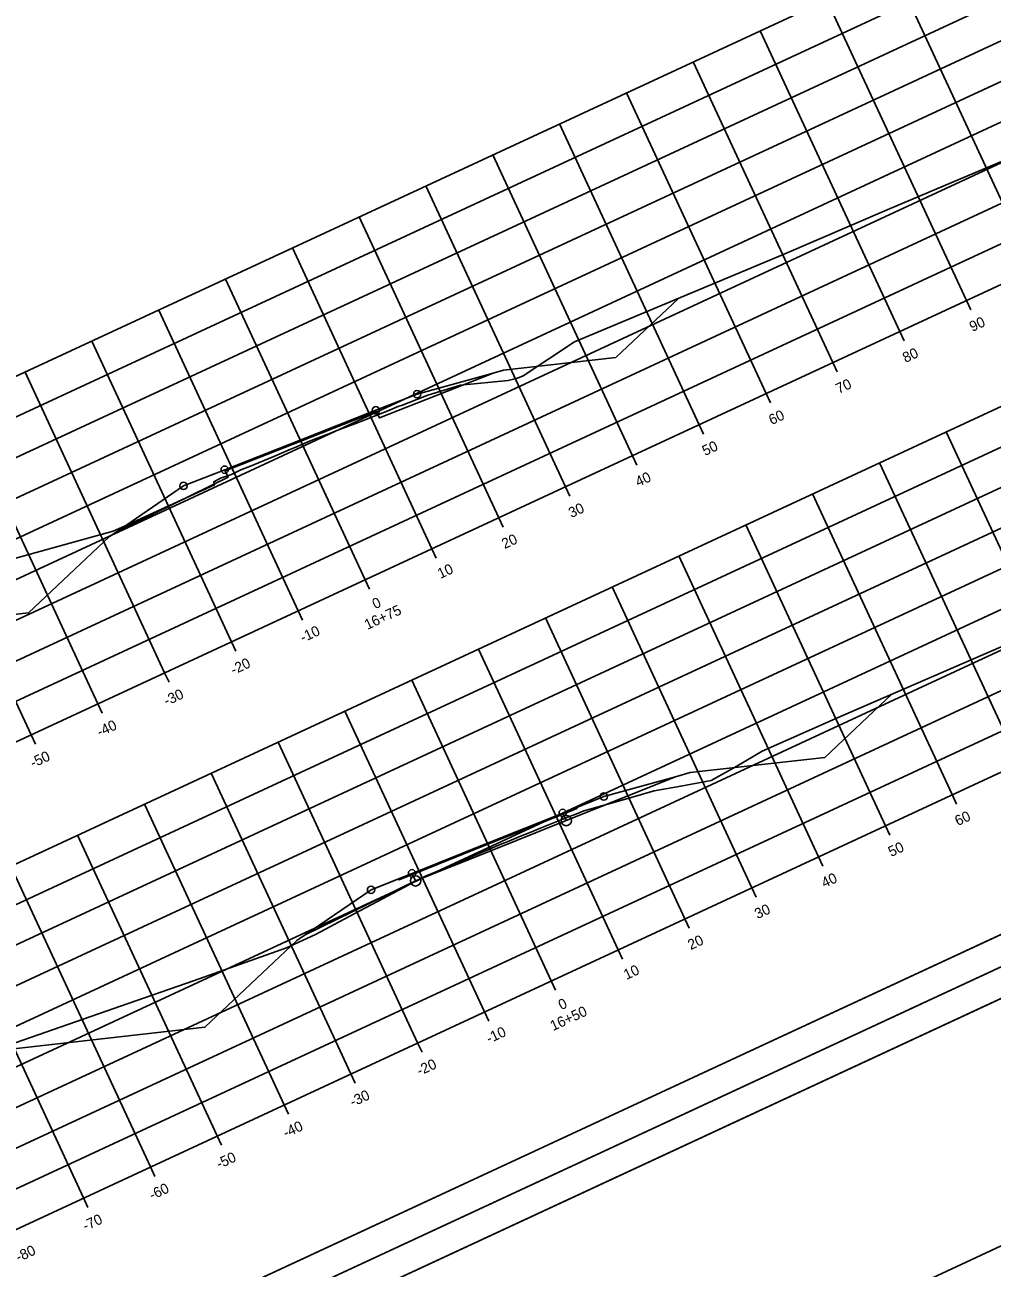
# Model space of a CAD drawing. Extents: x 1354696 to 1366163, y 660729 to 670380.
# Drawn here: x 1358666.2 to 1358797.4, y 666347.2 to 666515.9 of the extents above; entities that cross this region are included whole.
import ezdxf

# ---------------------------------------------------------------- set-up
doc = ezdxf.new("R2010")
doc.units = 0
for name, color, linetype in [('R_Alt Surface', 7, 'Continuous'), ('R_Axis', 7, 'Continuous'), ('R_Axis Annot', 7, 'Continuous'), ('R_Border', 7, 'Continuous'), ('R_Exist Surface', 7, 'Continuous'), ('R_Fin Surface', 7, 'Continuous'), ('R_Grid', 7, 'Continuous'), ('R_No Plot', 7, 'Continuous')]:
    doc.layers.add(name, color=color, linetype=linetype)

msp = doc.modelspace()

# ---------------------------------------------------------------- linework, layer by layer
at = {"layer": 'R_Alt Surface'}
for p, q in [((1358739.16, 666408.98), (1358741.02, 666409.73)), ((1358739.24, 666408.83), (1358741.09, 666409.57)), ((1358716.87, 666400.05), (1358718.71, 666400.79)), ((1358716.94, 666399.89), (1358718.78, 666400.63))]:
    msp.add_line(p, q, dxfattribs=at)
for points in [[(1358678.54, 666447.11), (1358693.74, 666454.55), (1358693.35, 666455.42), (1358703.61, 666459.45), (1358713.86, 666463.48), (1358714.27, 666462.61), (1358729.7, 666468.68)], [(1358704.2, 666392.44), (1358719.19, 666399.77), (1358729.41, 666403.86), (1358739.64, 666407.96), (1358754.46, 666413.9)], [(1358718.71, 666400.79), (1358728.94, 666404.89), (1358739.16, 666408.98)], [(1358718.78, 666400.63), (1358729.01, 666404.73), (1358739.24, 666408.83)]]:
    msp.add_lwpolyline(points, dxfattribs=at)
for points in [[(1358714.27, 666462.61), (1358713.86, 666463.48), (1358713.79, 666463.63), (1358719.39, 666465.83), (1358729.7, 666468.68)], [(1358693.28, 666455.57), (1358693.35, 666455.42), (1358693.74, 666454.55), (1358678.54, 666447.11), (1358687.69, 666453.37)], [(1358741.02, 666409.73), (1358741.09, 666409.57), (1358739.24, 666408.83), (1358739.64, 666407.96), (1358754.46, 666413.9), (1358744.74, 666411.22)], [(1358716.87, 666400.05), (1358716.94, 666399.89), (1358718.78, 666400.63), (1358719.19, 666399.77), (1358704.2, 666392.44), (1358713.14, 666398.55)]]:
    msp.add_lwpolyline(points, close=True, dxfattribs=at)
at = {"layer": 'R_Axis'}
for p, q in [((1358576.29, 666377.46), (1358848.4, 666503.79)), ((1358794.56, 666477.26), (1358793.97, 666478.53)), ((1358785.49, 666473.05), (1358784.9, 666474.32)), ((1358776.42, 666468.84), (1358775.83, 666470.11)), ((1358767.35, 666464.63), (1358766.76, 666465.9)), ((1358758.28, 666460.41), (1358757.69, 666461.68)), ((1358749.21, 666456.2), (1358748.62, 666457.47)), ((1358740.14, 666451.99), (1358739.55, 666453.26)), ((1358601.56, 666323.04), (1358873.66, 666449.37)), ((1358731.07, 666447.78), (1358730.48, 666449.05)), ((1358722, 666443.57), (1358721.41, 666444.84)), ((1358712.93, 666439.36), (1358712.34, 666440.63)), ((1358703.86, 666435.15), (1358703.27, 666436.42)), ((1358694.79, 666430.94), (1358694.2, 666432.21)), ((1358685.72, 666426.73), (1358685.13, 666428)), ((1358676.65, 666422.52), (1358676.06, 666423.79)), ((1358667.58, 666418.3), (1358666.99, 666419.57)), ((1358792.62, 666410.2), (1358792.03, 666411.47)), ((1358783.55, 666405.99), (1358782.96, 666407.26)), ((1358774.48, 666401.78), (1358773.89, 666403.05)), ((1358765.41, 666397.57), (1358764.82, 666398.84)), ((1358756.34, 666393.36), (1358755.75, 666394.63)), ((1358747.27, 666389.15), (1358746.68, 666390.42)), ((1358738.2, 666384.94), (1358737.61, 666386.21)), ((1358729.13, 666380.73), (1358728.54, 666382)), ((1358720.06, 666376.52), (1358719.47, 666377.79)), ((1358710.99, 666372.31), (1358710.4, 666373.58)), ((1358701.92, 666368.09), (1358701.33, 666369.36)), ((1358692.85, 666363.88), (1358692.26, 666365.15)), ((1358683.78, 666359.67), (1358683.19, 666360.94)), ((1358674.71, 666355.46), (1358674.12, 666356.73))]:
    msp.add_line(p, q, dxfattribs=at)
at = {"layer": 'R_Border'}
for p, q in [((1358889.5, 666434.68), (1358602.72, 666301.53)), ((1358606.04, 666294.39), (1358892.82, 666427.53)), ((1358744.49, 666358.38), (1358744.49, 666358.38)), ((1358744.49, 666358.38), (1358744.49, 666358.38))]:
    msp.add_line(p, q, dxfattribs=at)
at = {"layer": 'R_Exist Surface'}
for points in [[(1358662.24, 666442.84), (1358678.15, 666447.23), (1358679.7, 666447.91), (1358691.9, 666453.52), (1358691.8, 666453.93), (1358692.73, 666454.43), (1358694.07, 666454.86), (1358694.31, 666454.96), (1358695.46, 666455.54), (1358696.76, 666456.05), (1358697.86, 666456.49), (1358699.95, 666457.37), (1358702.04, 666458.27), (1358702.7, 666458.56), (1358704.81, 666459.45), (1358705.47, 666459.72), (1358707.63, 666460.52), (1358708.28, 666460.78), (1358710.44, 666461.6), (1358711.09, 666461.85), (1358711.76, 666462.09), (1358714.96, 666463.38), (1358715.34, 666463.53), (1358716.92, 666464.18), (1358717.27, 666464.3), (1358719.36, 666465.12), (1358720.85, 666465.69), (1358725.3, 666467.03), (1358731.75, 666467.68), (1358733, 666467.98), (1358733.79, 666468.29), (1358740.74, 666472.91), (1358769.01, 666484.73), (1358783.2, 666490.85), (1358808.37, 666501.48)], [(1358647.64, 666371.81), (1358679.15, 666382.75), (1358689.04, 666386.2), (1358701.66, 666390.68), (1358705.62, 666392.47), (1358710.19, 666394.93), (1358719.14, 666399.69), (1358719.84, 666400.04), (1358720.55, 666400.4), (1358722.6, 666401.27), (1358725.14, 666402.33), (1358726.34, 666402.86), (1358727.9, 666403.52), (1358729.08, 666404.04), (1358730.65, 666404.72), (1358731.84, 666405.18), (1358733.45, 666405.82), (1358734.6, 666406.3), (1358736.23, 666406.96), (1358737.8, 666407.59), (1358740.1, 666408.5), (1358740.92, 666408.84), (1358742.01, 666409.29), (1358746.72, 666410.59), (1358751.55, 666411.98), (1358755.17, 666412.64), (1358759.29, 666413.38), (1358762.78, 666415.35), (1358766.21, 666417.35), (1358776.53, 666421.96), (1358809.22, 666436.09)]]:
    msp.add_lwpolyline(points, dxfattribs=at)
at = {"layer": 'R_Fin Surface'}
for points in [[(1358631.18, 666432.12), (1358666.67, 666436.15), (1358677.64, 666446.5), (1358678.54, 666447.11), (1358687.69, 666453.37), (1358693.28, 666455.57), (1358703.54, 666459.6), (1358713.79, 666463.63), (1358719.39, 666465.83), (1358729.7, 666468.68), (1358731.11, 666469.07), (1358746.38, 666470.8), (1358754.88, 666478.82)], [(1358661.41, 666376.59), (1358690.6, 666379.9), (1358703.09, 666391.69), (1358704.2, 666392.44), (1358713.14, 666398.55), (1358718.71, 666400.79), (1358728.94, 666404.89), (1358739.16, 666408.98), (1358744.74, 666411.22), (1358754.46, 666413.9), (1358756.47, 666414.46), (1358774.74, 666416.53), (1358783.84, 666425.12)]]:
    msp.add_lwpolyline(points, dxfattribs=at)
at = {"layer": 'R_Grid'}
for p, q in [((1358557.34, 666418.28), (1358829.45, 666544.61)), ((1358559.45, 666413.74), (1358831.55, 666540.07)), ((1358561.55, 666409.21), (1358833.66, 666535.54)), ((1358563.66, 666404.67), (1358835.76, 666531)), ((1358565.76, 666400.14), (1358837.87, 666526.47)), ((1358803.04, 666482.74), (1358784.1, 666523.55)), ((1358567.87, 666395.6), (1358839.97, 666521.93)), ((1358793.97, 666478.53), (1358775.03, 666519.34)), ((1358569.97, 666391.07), (1358842.08, 666517.4)), ((1358784.9, 666474.32), (1358765.95, 666515.13)), ((1358572.08, 666386.53), (1358844.18, 666512.86)), ((1358775.83, 666470.11), (1358756.88, 666510.92)), ((1358574.19, 666382), (1358846.29, 666508.33)), ((1358766.76, 666465.9), (1358747.81, 666506.71)), ((1358576.29, 666377.46), (1358848.4, 666503.79)), ((1358757.69, 666461.68), (1358738.74, 666502.5)), ((1358748.62, 666457.47), (1358729.67, 666498.29)), ((1358739.55, 666453.26), (1358720.6, 666494.08)), ((1358582.61, 666363.86), (1358854.71, 666490.19)), ((1358730.48, 666449.05), (1358711.53, 666489.87)), ((1358584.71, 666359.32), (1358856.82, 666485.65)), ((1358721.41, 666444.84), (1358702.46, 666485.66)), ((1358586.82, 666354.79), (1358858.92, 666481.12)), ((1358712.34, 666440.63), (1358693.39, 666481.44)), ((1358588.92, 666350.25), (1358861.03, 666476.58)), ((1358703.27, 666436.42), (1358684.32, 666477.23)), ((1358591.03, 666345.72), (1358863.13, 666472.05)), ((1358694.2, 666432.21), (1358675.25, 666473.02)), ((1358685.13, 666428), (1358666.18, 666468.81)), ((1358593.14, 666341.18), (1358865.24, 666467.51)), ((1358676.06, 666423.79), (1358657.11, 666464.6)), ((1358595.24, 666336.65), (1358867.35, 666462.98)), ((1358666.99, 666419.57), (1358648.04, 666460.39)), ((1358810.17, 666419.9), (1358791.22, 666460.71)), ((1358597.35, 666332.11), (1358869.45, 666458.44)), ((1358801.1, 666415.69), (1358782.15, 666456.5)), ((1358599.45, 666327.58), (1358871.56, 666453.91)), ((1358792.03, 666411.47), (1358773.08, 666452.29)), ((1358601.56, 666323.04), (1358873.66, 666449.37)), ((1358782.96, 666407.26), (1358764.01, 666448.08)), ((1358773.89, 666403.05), (1358754.94, 666443.87)), ((1358764.82, 666398.84), (1358745.87, 666439.66)), ((1358755.75, 666394.63), (1358736.8, 666435.45)), ((1358746.68, 666390.42), (1358727.73, 666431.23)), ((1358737.61, 666386.21), (1358718.66, 666427.02)), ((1358728.54, 666382), (1358709.59, 666422.81)), ((1358719.47, 666377.79), (1358700.52, 666418.6)), ((1358710.4, 666373.58), (1358691.45, 666414.39)), ((1358701.33, 666369.36), (1358682.38, 666410.18)), ((1358692.26, 666365.15), (1358673.31, 666405.97)), ((1358683.19, 666360.94), (1358664.24, 666401.76)), ((1358674.12, 666356.73), (1358655.17, 666397.55)), ((1358626.12, 666270.13), (1358898.23, 666396.46))]:
    msp.add_line(p, q, dxfattribs=at)
at = {"layer": 'R_No Plot'}
msp.add_line((1358593.15, 666292.7), (1358895.49, 666433.07), dxfattribs=at)
msp.add_line((1358593.15, 666292.7), (1358895.49, 666433.07), dxfattribs=at)
for points in [[(1358503.31, 666486.2), (1358805.65, 666626.57), (1358895.49, 666433.07), (1358593.15, 666292.7)], [(1358728.37, 666586.39), (1358746.17, 666594.66), (1358750.33, 666585.69), (1358764.94, 666592.48), (1358785.98, 666602.25), (1358797.95, 666576.76), (1358819, 666586.53), (1358889.5, 666434.68), (1358602.72, 666301.53), (1358516.2, 666487.89)], [(1358593.15, 666292.7), (1358895.49, 666433.07), (1358985.33, 666239.57), (1358682.98, 666099.2)], [(1358818.21, 666392.89), (1358836.01, 666401.15), (1358840.17, 666392.19), (1358854.78, 666398.98), (1358875.82, 666408.75), (1358887.79, 666383.26), (1358908.84, 666393.03), (1358979.34, 666241.18), (1358692.56, 666108.03), (1358606.04, 666294.39)]]:
    msp.add_lwpolyline(points, close=True, dxfattribs=at)
for centre, radius in [((1358719.39, 666465.83), 0.5), ((1358713.79, 666463.63), 0.5), ((1358693.28, 666455.57), 0.5), ((1358687.69, 666453.37), 0.5), ((1358744.74, 666411.22), 0.5), ((1358739.16, 666408.98), 0.5), ((1358739.64, 666407.96), 0.7), ((1358718.71, 666400.79), 0.5), ((1358713.14, 666398.55), 0.5), ((1358719.19, 666399.77), 0.7)]:
    msp.add_circle(centre, radius, dxfattribs=at)

# ---------------------------------------------------------------- texts
at = {"layer": 'R_Axis Annot'}
for s, p in [('90', (1358794.76, 666474.26)), ('80', (1358785.69, 666470.05)), ('70', (1358776.62, 666465.84)), ('60', (1358767.52, 666461.61)), ('50', (1358758.48, 666457.42)), ('40', (1358749.41, 666453.21)), ('30', (1358740.34, 666449)), ('20', (1358731.27, 666444.78)), ('10', (1358722.56, 666440.74)), ('0', (1358713.7, 666436.63)), ('16+75', (1358712.64, 666433.82)), ('-10', (1358703.9, 666432.08)), ('-20', (1358694.47, 666427.7)), ('-30', (1358685.4, 666423.49)), ('-40', (1358676.33, 666419.28)), ('-50', (1358667.26, 666415.07)), ('60', (1358792.78, 666407.19)), ('50', (1358783.74, 666403)), ('40', (1358774.67, 666398.79)), ('30', (1358765.6, 666394.57)), ('20', (1358756.53, 666390.36)), ('10', (1358747.82, 666386.32)), ('0', (1358738.96, 666382.21)), ('16+50', (1358737.85, 666379.37)), ('-10', (1358729.16, 666377.66)), ('-20', (1358719.73, 666373.28)), ('-30', (1358710.66, 666369.07)), ('-40', (1358701.59, 666364.86)), ('-50', (1358692.52, 666360.65)), ('-60', (1358683.42, 666356.42)), ('-70', (1358674.38, 666352.22)), ('-80', (1358665.31, 666348.01))]:
    msp.add_text(s, height=1.4, rotation=24.9042, dxfattribs=at).set_placement(p)

doc.saveas('drawing.dxf')
